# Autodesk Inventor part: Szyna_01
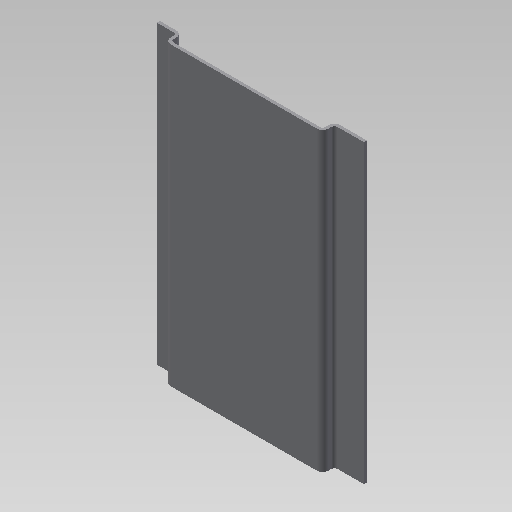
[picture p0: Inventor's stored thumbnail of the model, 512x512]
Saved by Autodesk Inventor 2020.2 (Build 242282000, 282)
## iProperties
Created: 2014-09
Part Number: Szyna_01
Material: Ogólny
Document SubType Name: Konstrukcja blachowa
Designer: F.Stasiak
Density: 1 g/cm^3
Sheet Metal Rule: Domyślny_mm
Appearance: Domyślna
Catalog Web Link: www.expertbooks.pl
Manager: www.cadconsulting.pl
Company: Fabian Stasiak CAD Consulting
Author: F.Stasiak
Subject: Zbiór ćwiczeń. Autodesk Inventor 2020. Kurs Professional
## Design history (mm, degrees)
node "Kołnierz z profilu1"
  sketch "Szkic1"
    geometry: L1 (-55, -6)-(-40, -6); L2 (-40, -6)-(-40, 0); L3 (-40, 0)-(40, 0); L4 (40, 0)-(40, -6); L5 (40, -6)-(50, -6); 2 further points
    constraints: 10 end point, 3 perpendicular, 2 point on line, 1 coincident, 1 horizontal, 1 midpoint
    dimensions: "d0" = 15 distance of L1.start L1.end; "d1" = 6 distance of L1.end L2.end; "d2" = 80 distance of L2.end L3.end; "d3" = 10 distance of L4.end L5.end
node "Bryła1"
feature "Płyta1" dims "d4" = 1.5 (= SzerokośćGięciaPodcięcia), "d5" = 0.75 (= GłębokośćGięciaPodcięcia), "d6" = 3 (= MinimalnaPozostałość), "d7" = 1.5 (= PromieńGięcia), "d8" = 150, "d9" = 1.5 (= PromieńGięcia), "d10" = 1.5, "d11" = 6 (= RozmiarPodcięciaNarożnika), "d12" = 1.5 (= Wielk_odstępu), "d13" = 1.5 (= Rozmiar_promienia_Jacobiego), "d14" = 1.5 (= Grubość), "OdstępPołączenia" = 0.01
feature "Gięcie1" dims "d4" = 1.5 (= SzerokośćGięciaPodcięcia), "d5" = 0.75 (= GłębokośćGięciaPodcięcia), "d6" = 3 (= MinimalnaPozostałość), "d7" = 1.5 (= PromieńGięcia), "d9" = 1.5 (= PromieńGięcia), "d10" = 1.5, "d14" = 1.5 (= Grubość), "OdstępPołączenia" = 0.01
feature "Narożnik1" dims "d10" = 1.5, "d11" = 6 (= RozmiarPodcięciaNarożnika), "d12" = 1.5 (= Wielk_odstępu), "d13" = 1.5 (= Rozmiar_promienia_Jacobiego)
other parameters: "Grubość" = 1.5 (derived), "WspółczynnikK" = 4.4, "PromieńGięcia" = 1.5 (= Grubość), "SzerokośćGięciaPodcięcia" = 1.5 (= Grubość), "GłębokośćGięciaPodcięcia" = 0.75 (= 0.5 x Grubość), "RozmiarPodcięciaNarożnika" = 6 (= 4 x Grubość), "MinimalnaPozostałość" = 3 (= 2 x Grubość), "PromieńPrzejścia" = 1.5 (= PromieńGięcia), "Rozmiar_promienia_Jacobiego" = 1.5 (= PromieńGięcia), "Wielk_odstępu" = 1.5 (= Grubość)
